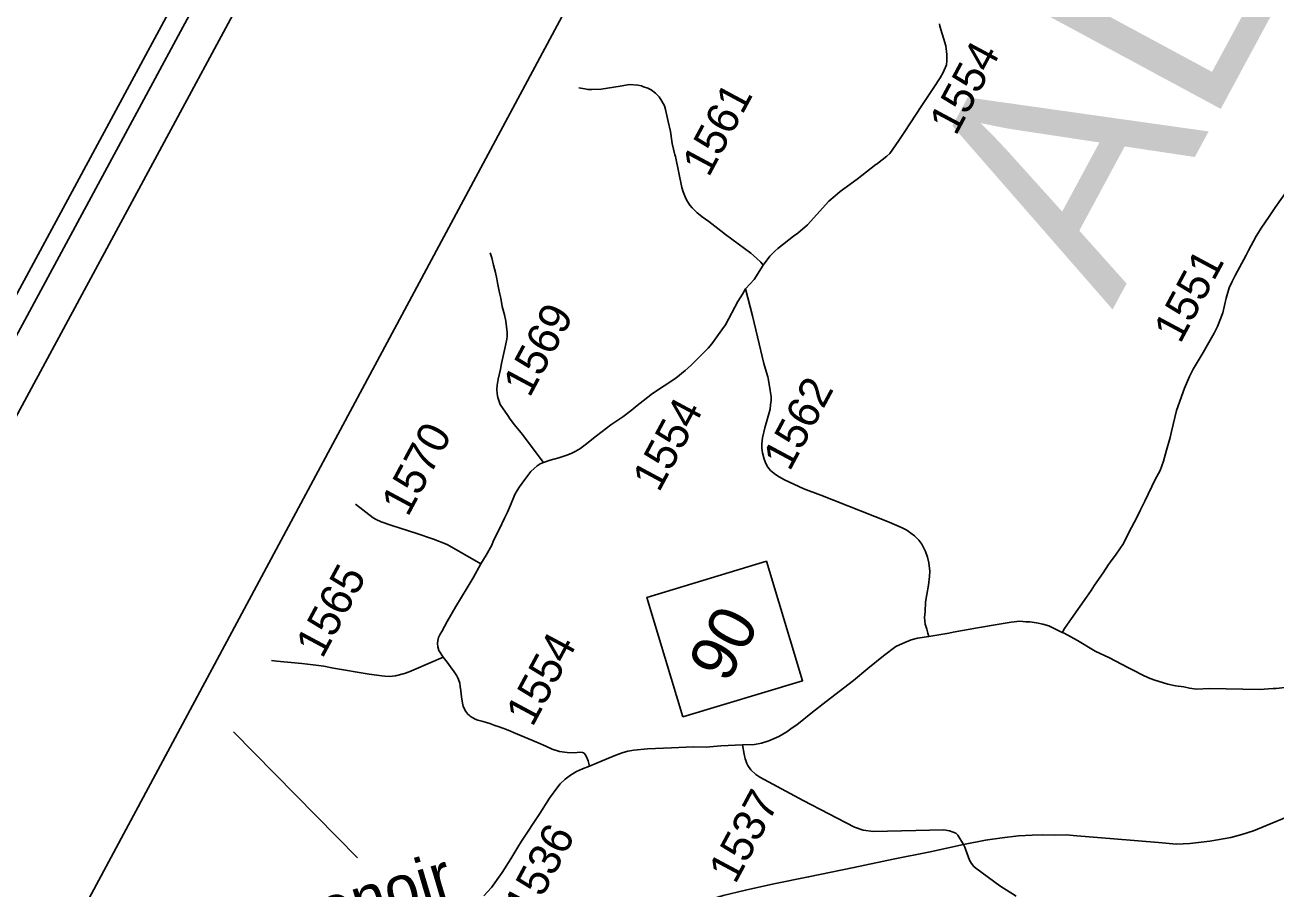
# Model space of a CAD drawing. Extents: x 1376167 to 1379209, y 761324 to 763997.
# Drawn here: x 1376443.7 to 1376608.1, y 762900.9 to 763014.5 of the extents above; entities that cross this region are included whole.
import ezdxf

# ---------------------------------------------------------------- set-up
doc = ezdxf.new("R2010")
doc.units = 0
for name, color, linetype in [('Default', 7, 'Continuous'), ('Old_Level_1', 7, 'Continuous'), ('Sheet Data Field CELL', 7, 'Continuous'), ('Sheet Plot Border Inside CELL', 7, 'Continuous'), ('Sheet Title CELL', 7, 'Continuous')]:
    doc.layers.add(name, color=color, linetype=linetype)

msp = doc.modelspace()

# ---------------------------------------------------------------- linework, layer by layer
at = {"layer": 'Default'}
for p, q in [((1376583.8, 762940.16), (1376584.27, 762940.87)), ((1376580.1, 762934.76), (1376580.02, 762934.64)), ((1376580.31, 762935.17), (1376580.1, 762934.76)), ((1376535.12, 762919.7), (1376537.97, 762919.86))]:
    msp.add_line(p, q, dxfattribs=at)
for points in [[(1376540.69, 762982.93), (1376541.58, 762984.13), (1376542.23, 762984.79), (1376542.61, 762985.14), (1376544.7, 762986.75), (1376545.25, 762987.13), (1376546.54, 762988.26), (1376549.34, 762991.34), (1376550.15, 762992.06), (1376550.83, 762992.64), (1376553.06, 762994.23), (1376555.52, 762996.16), (1376555.68, 762996.26), (1376555.74, 762996.3), (1376556.98, 762997.25), (1376557.34, 762997.64), (1376558.55, 762999.33), (1376559.25, 763000.38), (1376561.56, 763003.95), (1376563.13, 763006.28), (1376563.97, 763007.59), (1376564.36, 763008.28), (1376564.81, 763009.3), (1376564.86, 763009.79), (1376564.86, 763010.13), (1376564.86, 763010.65), (1376564.71, 763011.77), (1376563.93, 763014.38), (1376563.87, 763014.67)], [(1376540.69, 762982.93), (1376540.38, 762983.32), (1376539.82, 762983.84), (1376539.08, 762984.5), (1376535.75, 762986.98), (1376535.13, 762987.47), (1376533.58, 762988.67), (1376532.69, 762989.28), (1376531.98, 762989.87), (1376531.37, 762990.46), (1376531.07, 762990.83), (1376530.74, 762991.3), (1376530.55, 762991.69), (1376530.2, 762992.57), (1376530.01, 762993.15), (1376529.16, 762997.22), (1376529.08, 762997.45), (1376528.75, 762998.92), (1376528.51, 763000.53), (1376528.2, 763001.83), (1376527.86, 763003.39), (1376527.72, 763003.87), (1376527.39, 763004.52), (1376527.04, 763005.09), (1376526.79, 763005.3), (1376526.57, 763005.55), (1376525.96, 763005.98), (1376525.53, 763006.21), (1376524.99, 763006.39), (1376524.69, 763006.53), (1376524.22, 763006.62), (1376523.15, 763006.7), (1376521.92, 763006.48), (1376520.22, 763006.23), (1376519.39, 763006.1), (1376518.2, 763006.02), (1376517.68, 763006.03), (1376517.26, 763006.11), (1376516.46, 763006.24)], [(1376627.71, 763006.98), (1376627.16, 763006.56), (1376626.28, 763005.8), (1376625.29, 763005.09), (1376624.2, 763004.26), (1376623.57, 763003.82), (1376622.54, 763003.36), (1376621.31, 763002.38), (1376620.6, 763001.76), (1376619.85, 763000.97), (1376618.64, 762999.74), (1376618.16, 762999.32), (1376616.75, 762998.37), (1376615.46, 762997.66), (1376612.44, 762995.95), (1376611.69, 762995.44), (1376611.25, 762995.02), (1376610.96, 762994.64), (1376610.68, 762994.3), (1376608.02, 762990.52), (1376607.13, 762989.22)], [(1376607.13, 762989.22), (1376606.25, 762987.95), (1376605.52, 762986.75), (1376604.49, 762984.87), (1376604.18, 762984.23), (1376602.74, 762981.58), (1376602.3, 762980.71), (1376601.95, 762979.95), (1376601.57, 762978.6), (1376601.14, 762976.67), (1376600.43, 762974.86), (1376599.98, 762974.01), (1376599.12, 762972.47), (1376598.56, 762971.47), (1376597.25, 762969.27), (1376596.73, 762968.3), (1376596.11, 762966.76), (1376595.03, 762963.8), (1376594.39, 762961.06)], [(1376506.14, 762964.61), (1376505.81, 762965.55), (1376505.75, 762966.02), (1376505.68, 762966.62), (1376505.74, 762967.17), (1376505.88, 762967.96), (1376506.18, 762969.26), (1376506.29, 762969.99), (1376506.58, 762971.17), (1376506.75, 762971.99), (1376507.01, 762973.19), (1376507.03, 762973.56), (1376507.04, 762973.76), (1376507.03, 762974.08), (1376506.97, 762974.83), (1376506.87, 762975.57), (1376506.7, 762976.4), (1376506.41, 762977.5), (1376506.21, 762978.59), (1376506.07, 762979.1), (1376505.96, 762979.74), (1376505.79, 762980.6), (1376505.67, 762981.12), (1376505.53, 762981.98), (1376505.25, 762982.94), (1376505.02, 762983.9), (1376504.83, 762984.55)], [(1376538.4, 762979.84), (1376539.51, 762981.04), (1376540.69, 762982.93)], [(1376526.15, 762966.04), (1376529.23, 762968.09), (1376530.47, 762969.07), (1376531.19, 762969.72), (1376532.72, 762971.26), (1376533.45, 762972.03), (1376533.94, 762972.61), (1376535.28, 762974.41), (1376535.74, 762975.11), (1376537.36, 762978.17), (1376537.97, 762979.11), (1376538.4, 762979.84)], [(1376540.83, 762957.4), (1376540.61, 762958.26), (1376540.52, 762958.85), (1376540.51, 762959.43), (1376540.62, 762960.24), (1376540.9, 762961.54), (1376541.61, 762964.01), (1376541.67, 762964.56), (1376541.76, 762965.15), (1376541.75, 762965.66), (1376541.64, 762966.47), (1376541.35, 762968.07), (1376541.3, 762968.24), (1376541.28, 762968.37), (1376540.78, 762969.99), (1376539.96, 762973.5), (1376539.28, 762976.27), (1376538.4, 762979.84)], [(1376511.81, 762957), (1376512.7, 762957.3), (1376513.82, 762957.61), (1376514.9, 762957.95), (1376515.47, 762958.16), (1376515.99, 762958.42), (1376516.6, 762958.8), (1376517.48, 762959.45), (1376518.61, 762960.37), (1376519.54, 762961.07), (1376520.68, 762961.92), (1376522.24, 762963), (1376523.34, 762963.83), (1376524.13, 762964.46), (1376524.94, 762965.11), (1376526.15, 762966.04)], [(1376509.07, 762960.65), (1376508.86, 762960.91), (1376508, 762961.95), (1376507.44, 762962.7), (1376507.13, 762963.15), (1376506.14, 762964.61)], [(1376511.81, 762957), (1376510.59, 762958.59), (1376509.07, 762960.65)], [(1376594.39, 762961.06), (1376594.2, 762960.27), (1376593.73, 762958.59), (1376593.34, 762957.15), (1376592.89, 762955.94)], [(1376503.6, 762943.65), (1376504.3, 762944.79), (1376505.02, 762946.11), (1376505.26, 762946.73), (1376506.02, 762948.25), (1376506.71, 762949.66), (1376507.1, 762950.46), (1376507.47, 762951.37), (1376508.04, 762952.77), (1376508.36, 762953.32), (1376508.68, 762953.79), (1376509.37, 762954.74), (1376510.18, 762955.8), (1376510.6, 762956.21), (1376510.99, 762956.56), (1376511.37, 762956.79), (1376511.81, 762957)], [(1376562.5, 762943.8), (1376562.31, 762944.54), (1376562.04, 762945.29), (1376561.55, 762946.26), (1376561.15, 762946.79), (1376560.58, 762947.34), (1376560.12, 762947.67), (1376559.59, 762948.08), (1376558.99, 762948.37), (1376557.26, 762949.15), (1376553.5, 762950.61), (1376548.28, 762952.69), (1376546.07, 762953.54), (1376543.51, 762954.69), (1376542.81, 762955.08), (1376542.31, 762955.42), (1376541.67, 762955.95), (1376541.31, 762956.38), (1376541.05, 762956.85), (1376540.83, 762957.4)], [(1376592.89, 762955.94), (1376592.23, 762954.74), (1376590.86, 762951.91), (1376590.26, 762950.69), (1376589.87, 762949.84), (1376588.74, 762947.68), (1376588.08, 762946.35), (1376587.09, 762944.93), (1376586.37, 762943.93), (1376586.11, 762943.55), (1376585.39, 762942.46), (1376584.27, 762940.87)], [(1376503.6, 762943.65), (1376499.15, 762946.18), (1376497.37, 762946.89), (1376495.04, 762947.67), (1376491.88, 762948.71), (1376490.49, 762949.2), (1376489.81, 762949.5), (1376489.42, 762949.71), (1376487.11, 762951.51)], [(1376498.64, 762931.4), (1376498.06, 762932.26), (1376497.95, 762932.73), (1376497.91, 762933.17), (1376497.94, 762933.57), (1376498.04, 762933.95), (1376498.26, 762934.4), (1376498.44, 762934.77), (1376499.14, 762936.06), (1376500.32, 762938.06), (1376501.8, 762940.52), (1376502.58, 762941.81), (1376503.6, 762943.65)], [(1376562.23, 762935.06), (1376562, 762935.74), (1376561.89, 762936.59), (1376561.99, 762937.37), (1376562.06, 762938.6), (1376562.22, 762939.61), (1376562.43, 762940.83), (1376562.58, 762942), (1376562.63, 762942.69), (1376562.5, 762943.8)], [(1376583.8, 762940.16), (1376583.19, 762939.28), (1376581.22, 762936.46), (1376580.31, 762935.17)], [(1376562.48, 762934.08), (1376565.13, 762934.54), (1376565.68, 762934.66), (1376568.9, 762935.26), (1376571.72, 762935.7), (1376573.29, 762935.98), (1376574.46, 762936.1), (1376575.24, 762936.01), (1376575.75, 762936.04), (1376576.63, 762935.9), (1376577.46, 762935.71), (1376578.24, 762935.5), (1376580.02, 762934.64)], [(1376537.97, 762919.86), (1376539.58, 762919.91), (1376540.48, 762920.08), (1376541.45, 762920.37), (1376542.74, 762920.95), (1376543.8, 762921.55), (1376544.5, 762922.09), (1376545.11, 762922.49), (1376547.19, 762924.13), (1376548.99, 762925.55), (1376552.57, 762928.31), (1376554.48, 762929.9), (1376556.5, 762931.55), (1376558.14, 762932.77), (1376559.03, 762933.2), (1376560.15, 762933.64), (1376560.99, 762933.87), (1376562.48, 762934.08)], [(1376562.48, 762934.08), (1376562.37, 762934.52), (1376562.23, 762935.06)], [(1376580.02, 762934.64), (1376580.27, 762934.52), (1376582.04, 762933.59), (1376584.36, 762932.18), (1376586.24, 762931.31), (1376588.63, 762930.01), (1376589.45, 762929.63)], [(1376607.74, 762927.24), (1376608.14, 762927.26), (1376610.03, 762927.5), (1376611.33, 762927.7), (1376612.39, 762927.79), (1376613.23, 762927.96), (1376613.71, 762928.04), (1376614.31, 762928.19), (1376616.43, 762928.98), (1376619.31, 762930.05), (1376620.92, 762930.8), (1376621.44, 762930.97), (1376621.57, 762931.04), (1376622.59, 762931.49), (1376623.33, 762931.97), (1376623.72, 762932.31), (1376623.8, 762932.35), (1376623.98, 762932.49), (1376625.4, 762933.77)], [(1376476.08, 762930.94), (1376476.79, 762930.87), (1376480.05, 762930.55), (1376481.56, 762930.38), (1376482.94, 762930.19), (1376484.22, 762929.95), (1376488.91, 762929.15), (1376489.9, 762929), (1376490.57, 762928.91), (1376490.96, 762928.88), (1376491.6, 762928.86), (1376492.39, 762928.94), (1376493.53, 762929.25), (1376494.16, 762929.45), (1376494.79, 762929.7), (1376497.03, 762930.67), (1376498.64, 762931.4)], [(1376502.3, 762923.55), (1376502.19, 762923.63), (1376502.1, 762923.71), (1376501.89, 762923.88), (1376501.6, 762924.23), (1376501.37, 762924.7), (1376501.27, 762924.94), (1376501.19, 762925.34), (1376501.05, 762926.15), (1376500.95, 762926.94), (1376500.89, 762927.51), (1376500.82, 762927.95), (1376500.65, 762928.44), (1376500.52, 762928.76), (1376500.44, 762928.94), (1376500.1, 762929.45), (1376499.6, 762930.13), (1376499.15, 762930.71), (1376498.64, 762931.4)], [(1376589.45, 762929.63), (1376590.51, 762929.04), (1376591.35, 762928.66), (1376592.05, 762928.41), (1376593.89, 762927.85), (1376594.91, 762927.62), (1376595.99, 762927.5), (1376596.74, 762927.32), (1376597.65, 762927.18)], [(1376597.65, 762927.18), (1376599.37, 762927.24), (1376605.93, 762927.13)], [(1376605.93, 762927.13), (1376607.74, 762927.24)], [(1376512.98, 762919.27), (1376512.13, 762919.66), (1376511.13, 762920.1), (1376507.89, 762921.47), (1376507.47, 762921.63), (1376506.96, 762921.88), (1376506.48, 762922.04), (1376505.85, 762922.28), (1376505.44, 762922.4), (1376504.97, 762922.57), (1376504.79, 762922.65), (1376504.35, 762922.78), (1376503.73, 762922.95), (1376503.19, 762923.11), (1376502.86, 762923.24), (1376502.3, 762923.55)], [(1376471.07, 762921.58), (1376487.37, 762904.97)], [(1376517.3, 762918.56), (1376517.19, 762918.75), (1376517.08, 762918.82), (1376516.94, 762918.86), (1376516.62, 762918.87), (1376515.89, 762918.82), (1376514.92, 762918.85), (1376513.92, 762918.97), (1376512.98, 762919.27)], [(1376517.85, 762917.06), (1376519.55, 762917.74), (1376521.35, 762918.51), (1376522.16, 762918.79), (1376522.92, 762919), (1376523.71, 762919.16), (1376525.51, 762919.31), (1376528.65, 762919.44), (1376531.54, 762919.59), (1376533.23, 762919.56), (1376535.12, 762919.7)], [(1376537.97, 762919.86), (1376538.2, 762918.61), (1376538.34, 762918.03), (1376538.42, 762917.8), (1376538.56, 762917.4), (1376538.68, 762917.15), (1376539.07, 762916.55), (1376539.75, 762915.96), (1376540.28, 762915.6), (1376545.95, 762912.55), (1376552.72, 762909.03), (1376553.87, 762908.61), (1376555.22, 762908.46), (1376564.44, 762908.69)], [(1376517.85, 762917.06), (1376517.68, 762917.74), (1376517.47, 762918.27), (1376517.3, 762918.56)], [(1376599.4, 762907.2), (1376600.43, 762907.36), (1376602.2, 762907.68), (1376603.65, 762908.07), (1376605.17, 762908.52), (1376606.97, 762909.27), (1376609.74, 762910.44), (1376615.81, 762912.77), (1376621, 762914.85), (1376624.37, 762916.24), (1376626.85, 762917.34)], [(1376504, 762900), (1376504.98, 762901.08), (1376506.38, 762903.06), (1376507.51, 762904.85), (1376508.46, 762906.38), (1376508.94, 762907.17), (1376511.33, 762910.84), (1376512.6, 762912.83), (1376513.69, 762914.33), (1376514.02, 762914.72), (1376514.69, 762915.33), (1376515.38, 762915.87), (1376516.16, 762916.35), (1376516.96, 762916.71), (1376517.85, 762917.06)], [(1376564.44, 762908.69), (1376565.18, 762908.55), (1376565.68, 762908.38), (1376566.03, 762908.22), (1376566.3, 762907.99), (1376567.02, 762906.76)], [(1376567.02, 762906.76), (1376569.94, 762907.33), (1376572.12, 762907.6), (1376574.26, 762907.89), (1376576.07, 762907.96), (1376577.39, 762908.03), (1376578.96, 762907.96), (1376580.54, 762908), (1376581.95, 762907.88), (1376586.78, 762907.5), (1376592.67, 762906.99), (1376595.02, 762906.78), (1376596.79, 762906.88), (1376599.4, 762907.2)], [(1376513.48, 762892.25), (1376515.77, 762893.08), (1376523.24, 762895.79), (1376528.64, 762897.76), (1376532.48, 762899.12), (1376535.43, 762900.03), (1376538.39, 762900.76), (1376542.11, 762901.59), (1376546.68, 762902.48), (1376552.64, 762903.7), (1376557.79, 762904.81), (1376562.66, 762905.79), (1376567.02, 762906.76)], [(1376567.02, 762906.76), (1376567.2, 762906.39), (1376567.29, 762906.11), (1376567.83, 762904.68)], [(1376567.83, 762904.68), (1376568.1, 762904.24), (1376568.41, 762903.87), (1376568.67, 762903.64), (1376571.81, 762901.33), (1376573.94, 762899.95)]]:
    msp.add_lwpolyline(points, dxfattribs=at)
msp.add_lwpolyline([(1376530.16, 762923.53), (1376525.41, 762939.25), (1376541.13, 762944), (1376545.88, 762928.27)], close=True, dxfattribs=at)
at = {"layer": 'Old_Level_1'}
for points in [[(1376622.61, 762553.05), (1376345.79, 762701.47), (1376550.88, 763083.99), (1376827.7, 762935.57)], [(1376345.79, 762701.47), (1376660.36, 762532.81), (1376865.45, 762915.33), (1376550.88, 763083.99)]]:
    msp.add_lwpolyline(points, close=True, dxfattribs=at)
at = {"layer": 'Sheet Plot Border Inside CELL'}
msp.add_lwpolyline([(1377121.6, 762015.28), (1377912.43, 763482.18), (1376983.7, 763982.88), (1376192.87, 762515.97)], close=True, dxfattribs=at)
at = {"layer": 'Sheet Title CELL'}
for points in [[(1376975.27, 763961.87), (1376272.92, 762659.12)], [(1376977.29, 763955.09), (1376303.44, 762705.17)]]:
    msp.add_lwpolyline(points, dxfattribs=at)

# ---------------------------------------------------------------- texts
at = {"layer": 'Default'}
for s, height, rotation, p in [('90', 6.103, 61.8015, (1376536, 762927.8)), ('To Lenoir', 6, 16.5293, (1376467.85, 762890.4))]:
    msp.add_text(s, height=height, rotation=rotation, dxfattribs=at).set_placement(p)
at = {"layer": 'Old_Level_1'}
for s, p in [('1554', (1376566.03, 762999.83)), ('1561', (1376533.54, 762994.38)), ('1551', (1376595.52, 762972.49)), ('1569', (1376509.99, 762965.4)), ('1562', (1376544.18, 762955.7)), ('1554', (1376527, 762952.94)), ('1570', (1376493.99, 762949.72)), ('1565', (1376482.74, 762931.07)), ('1554', (1376510.37, 762922.08)), ('1537', (1376537.03, 762901.42)), ('1536', (1376510.17, 762896.94))]:
    msp.add_text(s, height=4.185, rotation=61.8015, dxfattribs=at).set_placement(p)
at = {"layer": 'Sheet Data Field CELL'}
msp.add_text('          ALEXANDER          ', height=30, rotation=61.6702, dxfattribs=at).set_placement((1376533.71, 762878.93))

doc.saveas('drawing.dxf')
